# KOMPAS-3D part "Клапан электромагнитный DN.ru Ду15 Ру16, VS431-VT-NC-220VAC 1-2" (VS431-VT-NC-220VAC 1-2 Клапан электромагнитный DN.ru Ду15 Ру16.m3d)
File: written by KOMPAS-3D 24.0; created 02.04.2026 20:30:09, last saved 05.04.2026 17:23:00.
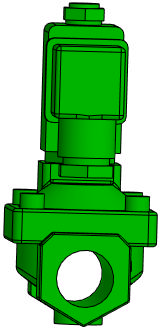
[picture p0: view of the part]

Document properties: Автор: artio; Полное имя файла: C:\Users\artio\OneDrive\Рабочий стол\Клапан электромагнитный DN.ru\VS431\VS431-VT-NC\VS431-VT-NC-220VAC\Ду15\VS431-VT-NC-220VAC 1-2 Клапан электромагнитный DN.ru Ду15 Ру16.m3d

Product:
- Body: Тело 1  | qty 1
    Масса: 1.030062
- Part/product: Клапан электромагнитный DN.ru Ду15 Ру16  | designation VS431-VT-NC-220VAC 1-2
    Масса: 0.732
    Раздел спецификации: Прочие изделия
    Примечание: D130-04712
    additional columns: ef56311e-7521-43dc-8291-0e6108b3d81d; VS400-ET-NC-220VAC 1-2; artio; c; Шероховатость не задана; Да

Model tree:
1. Операция без истории:1

Expressions: VS431-VT-NC-220VAC 1-2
